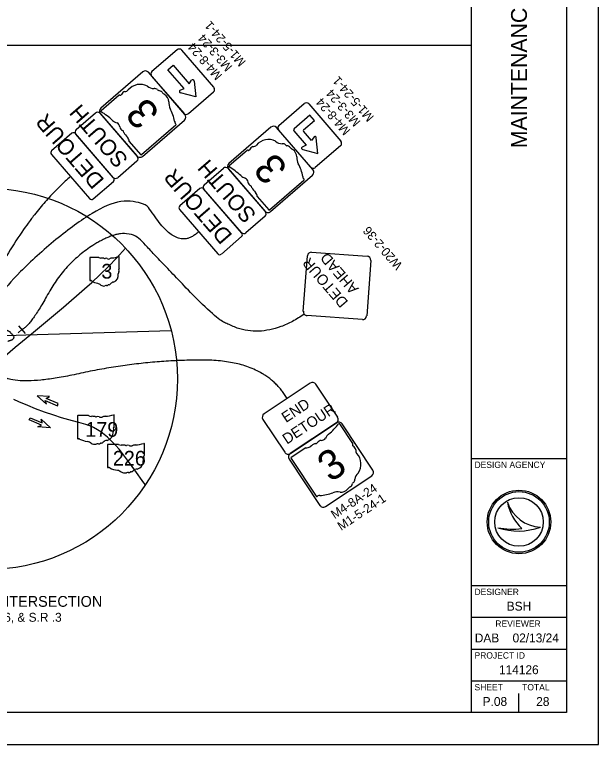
# Model space of a CAD drawing. Extents: x -15.3 to 34, y 0 to 22.
# Drawn here: x 24.81 to 34, y 0 to 11.48 of the extents above; entities that cross this region are included whole.
import ezdxf

# ---------------------------------------------------------------- set-up
doc = ezdxf.new("R2010")
doc.units = 0
for name, color, linetype in [('GM_X_State_Route', 7, 'Continuous'), ('GM_X_State_Shield', 7, 'Continuous'), ('GM_X_Township', 7, 'Continuous'), ('PM_P_Cells', 7, 'Continuous'), ('SC_Scratch1', 7, 'Continuous'), ('SH_Border', 7, 'Continuous'), ('SH_Cut_Line', 7, 'Continuous'), ('SH_Data', 7, 'Continuous'), ('SH_Text', 7, 'Continuous'), ('SN_P_Signs', 7, 'Continuous')]:
    doc.layers.add(name, color=color, linetype=linetype)

msp = doc.modelspace()

# ---------------------------------------------------------------- linework, layer by layer
at = {"layer": 'GM_X_State_Route'}
for points in [[(25.11, 6.489), (25.327, 6.672), (25.579, 6.881), (25.91, 7.167), (26.024, 7.269), (26.152, 7.389), (26.292, 7.526), (26.413, 7.653), (26.556, 7.81)], [(24.374, 5.874), (24.383, 5.882), (24.534, 6.008), (24.819, 6.248), (25.11, 6.489)], [(26.87, 4.084), (26.846, 4.118), (26.705, 4.313), (26.602, 4.454), (26.51, 4.577), (26.455, 4.645), (26.397, 4.71), (26.335, 4.773), (26.271, 4.833), (26.221, 4.876), (26.167, 4.916), (26.114, 4.952), (26.054, 4.984), (25.993, 5.01), (25.934, 5.031), (25.821, 5.064), (25.723, 5.091), (25.55, 5.141), (25.428, 5.178), (25.28, 5.23), (25.141, 5.282), (25.02, 5.331), (24.879, 5.392), (24.801, 5.429)]]:
    msp.add_lwpolyline(points, dxfattribs=at)
at = {"layer": 'GM_X_State_Shield'}
for p, q in [((25.995, 7.657), (25.995, 7.305)), ((26.136, 7.663), (26, 7.663)), ((26.459, 7.487), (26.459, 7.672)), ((26.459, 7.487), (26.459, 7.487)), ((25.976, 5.173), (25.806, 5.173)), ((26.38, 4.998), (26.38, 5.182)), ((25.8, 5.167), (25.8, 4.815)), ((26.38, 4.998), (26.38, 4.998)), ((26.273, 4.715), (26.273, 4.363)), ((26.448, 4.721), (26.279, 4.721)), ((26.853, 4.545), (26.853, 4.73)), ((26.853, 4.545), (26.853, 4.545))]:
    msp.add_line(p, q, dxfattribs=at)
for centre, radius, start, end in [((26, 7.658), 0.00538, 98.1301, 188.1301), ((26.168, 7.704), 0.0521, 231.6195, 271.1119), ((26.185, 7.465), 0.187, 80.4867, 94.9883), ((26.228, 7.659), 0.015, 219.7921, 297.1024), ((26.25, 7.619), 0.0313, 54.4667, 119.1411), ((26.29, 7.674), 0.0376, 233.8562, 294.8282), ((26.357, 7.555), 0.099, 97.3462, 120.7689), ((26.294, 8.143), 0.492, 275.8445, 288.9065), ((26.454, 7.672), 0.00517, 351.8621, 97.738), ((26.458, 7.474), 0.00799, 107.944, 210.337), ((26.407, 7.451), 0.048, 340.033, 23.6496), ((26.454, 7.487), 0.00553, 289.6038, 7.7341), ((26.321, 7.387), 0.123, 292.3089, 8.9858), ((26.478, 7.41), 0.0349, 136.8065, 186.9296), ((26, 7.304), 0.00542, 171.9584, 258.3066), ((26.001, 7.34), 0.0414, 267.339, 280.6039), ((26.01, 7.284), 0.0149, 29.7484, 93.2717), ((26.198, 7.601), 0.355, 240.4129, 257.1985), ((26.092, 7.146), 0.111, 47.1842, 75.836), ((26.288, 7.27), 0.0398, 282.8732, 323.2771), ((26.373, 7.206), 0.0674, 94.4031, 142.5768), ((26.212, 7.283), 0.0706, 230.7004, 286.2918), ((26.253, 7.161), 0.058, 85.6951, 111.2099), ((26.258, 7.256), 0.0376, 268.777, 315.5493), ((26.292, 7.222), 0.0106, 65.7517, 132.6484)]:
    msp.add_arc(centre, radius, start, end, dxfattribs=at)
for centre, major_axis, start_param, end_param in [((25.807, 5.168), (0.00672, 0), 1.712693, 3.28349), ((26.016, 5.214), (0.0652, 0), 4.042523, 4.731795), ((26.174, 5.653), (0.615, 0), 4.814394, 5.042369), ((26.374, 5.183), (0.00646, 0), 6.141152, 7.989035), ((26.038, 4.975), (0.234, 0), 1.404758, 1.657858), ((26.091, 5.17), (0.0188, 0), 3.836095, 5.185415), ((26.119, 5.129), (0.0391, 0), 0.950623, 2.079405), ((26.169, 5.185), (0.047, 0), 4.081561, 5.145723), ((26.252, 5.065), (0.124, 0), 1.699011, 2.107814), ((26.404, 4.92), (0.0436, 0), 2.387724, 3.262537), ((26.379, 4.984), (0.00999, 0), 1.883978, 3.671073), ((26.315, 4.961), (0.06, 0), 5.934695, 6.695948), ((26.374, 4.997), (0.00691, 0), 5.05454, 6.418171), ((26.208, 4.897), (0.154, 0), 5.101752, 6.440018), ((25.807, 4.814), (0.00678, 0), 3.00124, 4.508301), ((25.808, 4.85), (0.0517, 0), 4.665946, 4.897461), ((25.819, 4.794), (0.0187, 0), 0.519207, 1.627899), ((26.054, 5.111), (0.444, 0), 4.195997, 4.488961), ((25.922, 4.657), (0.139, 0), 0.823519, 1.323587), ((26.072, 4.793), (0.0882, 0), 4.026481, 4.996735), ((26.123, 4.671), (0.0725, 0), 1.495662, 1.94098), ((26.13, 4.766), (0.047, 0), 4.691044, 5.507374), ((26.172, 4.732), (0.0132, 0), 1.147584, 2.315152), ((26.166, 4.781), (0.0497, 0), 4.937069, 5.64225), ((26.273, 4.716), (0.0843, 0), 1.647645, 2.488434), ((26.28, 4.716), (0.00672, 0), 1.712693, 3.28349), ((26.489, 4.762), (0.0652, 0), 4.042523, 4.731795), ((26.511, 4.523), (0.234, 0), 1.404758, 1.657858), ((26.591, 4.677), (0.0391, 0), 0.950623, 2.079405), ((26.725, 4.613), (0.124, 0), 1.699011, 2.107814), ((26.646, 5.201), (0.615, 0), 4.814394, 5.042369), ((26.847, 4.73), (0.00646, 0), 6.141152, 7.989035), ((26.564, 4.717), (0.0188, 0), 3.836095, 5.185415), ((26.642, 4.733), (0.047, 0), 4.081561, 5.145723), ((26.876, 4.468), (0.0436, 0), 2.387724, 3.262537), ((26.851, 4.532), (0.00999, 0), 1.883978, 3.671073), ((26.788, 4.509), (0.06, 0), 5.934695, 6.695948), ((26.846, 4.545), (0.00691, 0), 5.05454, 6.418171), ((26.681, 4.445), (0.154, 0), 5.101752, 6.440018), ((26.28, 4.362), (0.00678, 0), 3.00124, 4.508301), ((26.281, 4.398), (0.0517, 0), 4.665946, 4.897461), ((26.291, 4.342), (0.0187, 0), 0.519207, 1.627899), ((26.527, 4.659), (0.444, 0), 4.195997, 4.488961), ((26.394, 4.204), (0.139, 0), 0.823519, 1.323587), ((26.545, 4.341), (0.0882, 0), 4.026481, 4.996735), ((26.596, 4.219), (0.0725, 0), 1.495662, 1.94098), ((26.602, 4.314), (0.047, 0), 4.691044, 5.507374), ((26.645, 4.28), (0.0132, 0), 1.147584, 2.315152), ((26.639, 4.328), (0.0497, 0), 4.937069, 5.64225), ((26.746, 4.264), (0.0843, 0), 1.647645, 2.488434)]:
    msp.add_ellipse(centre, major_axis=major_axis, ratio=0.8, start_param=start_param, end_param=end_param, dxfattribs=at)
at = {"layer": 'GM_X_Township'}
msp.add_lwpolyline([(21.433, 6.335), (21.992, 6.347), (24.231, 6.418), (24.989, 6.443), (27.276, 6.515)], dxfattribs=at)
at = {"layer": 'PM_P_Cells'}
for p, q in [((25.164, 5.487), (25.164, 5.487)), ((25.164, 5.487), (25.311, 5.353)), ((25.362, 5.473), (25.164, 5.487)), ((25.311, 5.353), (25.294, 5.41)), ((25.294, 5.41), (25.484, 5.329)), ((25.309, 5.445), (25.362, 5.473)), ((25.499, 5.364), (25.309, 5.445)), ((25.484, 5.329), (25.499, 5.364)), ((25.491, 5.346), (25.491, 5.346)), ((25.042, 5.106), (25.057, 5.14)), ((25.232, 5.025), (25.042, 5.106)), ((25.049, 5.123), (25.049, 5.123)), ((25.057, 5.14), (25.246, 5.059)), ((25.246, 5.059), (25.23, 5.116)), ((25.23, 5.116), (25.377, 4.983)), ((25.179, 4.997), (25.232, 5.025)), ((25.377, 4.983), (25.179, 4.997)), ((25.377, 4.983), (25.377, 4.983))]:
    msp.add_line(p, q, dxfattribs=at)
at = {"layer": 'SH_Border'}
for p, q in [((32, 0.5), (32, 21.5)), ((32, 4.5), (33.5, 4.5)), ((32, 2.5), (33.5, 2.5)), ((32, 2), (33.5, 2)), ((32, 1.5), (33.5, 1.5)), ((32, 1), (33.5, 1))]:
    msp.add_line(p, q, dxfattribs=at)
msp.add_lwpolyline([(1.5, 21.5), (33.5, 21.5), (33.5, 0.5), (1.5, 0.5)], close=True, dxfattribs=at)
at = {"layer": 'SH_Cut_Line'}
msp.add_lwpolyline([(0, 0), (34, 0), (34, 22), (0, 22)], close=True, dxfattribs=at)
at = {"layer": 'SH_Data'}
for p, q in [((32.567, 3.81), (32.567, 3.81)), ((32.75, 3.5), (32.75, 3.5)), ((32.417, 3.41), (32.417, 3.41)), ((33.087, 3.419), (33.087, 3.419)), ((32.75, 0.5), (32.75, 0.8)), ((32.375, 0.675), (32.375, 0.675))]:
    msp.add_line(p, q, dxfattribs=at)
for radius in [0.5, 0.477, 0.477, 0.382]:
    msp.add_circle((32.75, 3.5), radius, dxfattribs=at)
for centre, radius, start, end in [((33.116, 3.998), 0.58, 198.9257, 198.9319), ((33.347, 3.97), 0.796, 191.6379, 191.6421), ((33.116, 3.998), 0.58, 198.9319, 267.1657), ((33.347, 3.97), 0.796, 191.6421, 226.0947), ((32.739, 4.37), 1.013, 251.4576, 290.0832), ((32.648, 4.654), 1.266, 259.4964, 259.4995), ((32.739, 4.37), 1.013, 251.4527, 251.4576), ((32.648, 4.654), 1.266, 259.4995, 276.6672)]:
    msp.add_arc(centre, radius, start, end, dxfattribs=at)
at = {"layer": 'SH_Text'}
msp.add_line((1.5, 11), (32, 11), dxfattribs=at)
msp.add_circle((24.375, 5.75), 3, dxfattribs=at)
for points in [[(25.691, 8.936), (25.108, 8.44), (24.059, 6.582), (24.722, 6.238), (24.482, 6.158)], [(27.707, 8.067), (27.378, 7.746), (26.619, 8.935), (24.147, 6.818), (24.949, 6.395), (24.704, 6.342)], [(29.37, 6.769), (28.492, 6.169), (27.047, 7.664), (26.581, 8.173), (25.618, 7.599), (25.062, 6.587), (24.926, 6.527)], [(29.1, 5.444), (28.747, 6.047), (26.796, 6.047), (24.861, 5.622), (24.609, 5.799)]]:
    msp.add_open_spline(points, degree=2, dxfattribs=at)
at = {"layer": 'SN_P_Signs'}
for p, q in [((27.371, 10.93), (26.973, 10.587)), ((27.948, 10.339), (27.441, 10.925)), ((27.223, 10.616), (27.305, 10.688)), ((27.305, 10.688), (27.561, 10.392)), ((27.478, 10.321), (27.223, 10.616)), ((26.968, 10.516), (27.475, 9.93)), ((26.968, 10.516), (26.968, 10.516)), ((27.561, 10.392), (27.596, 10.449)), ((27.635, 10.437), (27.662, 10.191)), ((27.416, 10.294), (27.478, 10.321)), ((27.662, 10.191), (27.42, 10.254)), ((27.546, 9.925), (27.943, 10.268)), ((26.455, 10.215), (26.173, 9.971)), ((26.455, 10.215), (26.455, 10.215)), ((28.972, 9.739), (29.369, 10.082)), ((29.44, 10.077), (29.947, 9.491)), ((25.78, 9.674), (26.083, 9.935)), ((26.153, 9.93), (26.742, 9.249)), ((29.458, 9.901), (29.21, 9.686)), ((29.53, 9.818), (29.458, 9.901)), ((29.53, 9.818), (29.458, 9.901)), ((29.358, 9.67), (29.53, 9.818)), ((26.809, 9.282), (27.347, 9.747)), ((29.474, 9.082), (28.967, 9.668)), ((29.207, 9.653), (29.402, 9.428)), ((29.207, 9.653), (29.207, 9.653)), ((29.484, 9.5), (29.357, 9.648)), ((26.363, 8.922), (25.775, 9.603)), ((29.524, 9.562), (29.484, 9.5)), ((29.586, 9.299), (29.558, 9.544)), ((26.614, 9.488), (26.793, 9.281)), ((29.402, 9.428), (29.335, 9.398)), ((29.942, 9.42), (29.544, 9.077)), ((28.471, 9.346), (28.19, 9.103)), ((28.471, 9.346), (28.471, 9.346)), ((29.347, 9.362), (29.586, 9.299)), ((26.736, 9.179), (26.434, 8.917)), ((27.797, 8.805), (28.099, 9.067)), ((28.17, 9.062), (28.758, 8.381)), ((28.825, 8.413), (29.364, 8.878)), ((28.38, 8.054), (27.791, 8.735)), ((28.631, 8.62), (28.81, 8.412)), ((28.753, 8.31), (28.45, 8.049)), ((24.873, 6.587), (24.978, 6.466)), ((24.926, 6.527), (24.865, 6.474)), ((30.134, 4.732), (29.928, 5.042)), ((30.134, 4.732), (30.134, 4.732)), ((29.393, 4.666), (29.164, 4.515)), ((29.163, 4.499), (29.557, 3.906))]:
    msp.add_line(p, q, dxfattribs=at)
for points in [[(26.83, 10.581), (26.168, 10.009)], [(27.49, 9.913), (26.918, 10.575)], [(26.161, 9.921), (26.733, 9.259)], [(26.822, 9.252), (27.484, 9.824)], [(28.846, 9.713), (28.184, 9.14)], [(29.507, 9.044), (28.934, 9.706)], [(25.712, 9.615), (25.394, 9.34)], [(26.37, 8.915), (25.768, 9.611)], [(25.39, 9.284), (25.992, 8.588)], [(28.178, 9.052), (28.75, 8.39)], [(26.048, 8.584), (26.366, 8.858)], [(28.838, 8.384), (29.5, 8.956)], [(27.728, 8.746), (27.411, 8.472)], [(28.386, 8.046), (27.785, 8.742)], [(27.407, 8.415), (28.008, 7.719)], [(28.065, 7.715), (28.382, 7.99)], [(29.486, 7.745), (30.358, 7.681)], [(29.355, 6.814), (29.419, 7.687)], [(30.416, 7.614), (30.353, 6.742)], [(30.286, 6.684), (29.413, 6.748)], [(29.463, 5.684), (28.738, 5.203)], [(29.896, 5.149), (29.553, 5.666)], [(28.719, 5.113), (29.062, 4.597)], [(29.879, 5.061), (29.15, 4.577)], [(29.152, 4.578), (29.877, 5.059)], [(30.45, 4.314), (29.966, 5.043)], [(29.133, 4.49), (29.616, 3.761)], [(29.703, 3.744), (30.432, 4.227)]]:
    msp.add_lwpolyline(points, dxfattribs=at)
for centre, radius, start, end in [((27.403, 10.892), 0.05, 40.8371, 130.8371), ((26.87, 10.534), 0.0625, 40.8371, 130.8371), ((27.006, 10.549), 0.05, 130.8371, 220.8371), ((27.614, 10.438), 0.0209, 355.8276, 148.0417), ((26.79, 10.137), 0.249, 63.146, 139.823), ((26.999, 10.456), 0.136, 225.2403, 273.4139), ((27.91, 10.306), 0.05, 310.8371, 40.8371), ((26.477, 10.231), 0.0162, 238.7811, 341.1741), ((26.58, 10.184), 0.097, 110.8701, 154.4867), ((26.548, 10.345), 0.0705, 267.6436, 317.7667), ((27.012, 10.239), 0.0803, 53.7103, 94.1143), ((27.081, 10.31), 0.0214, 196.5889, 263.4856), ((27.073, 10.213), 0.0759, 39.6142, 86.3864), ((27.226, 10.331), 0.117, 216.5323, 242.0471), ((27.094, 10.108), 0.143, 1.5375, 57.129), ((27.425, 10.275), 0.0209, 113.6325, 255.4259), ((26.463, 10.207), 0.0112, 60.441, 138.5713), ((27.461, 10.104), 0.225, 178.0213, 206.6731), ((26.208, 9.962), 0.0625, 130.8371, 220.8371), ((26.626, 9.666), 0.718, 11.2501, 28.0356), ((29.402, 10.044), 0.05, 40.8371, 130.8371), ((26.115, 9.897), 0.05, 40.8371, 130.8371), ((26.179, 9.962), 0.0104, 122.6992, 228.5751), ((25.671, 9.096), 0.994, 46.6816, 59.7436), ((27.513, 9.963), 0.05, 220.8371, 310.8371), ((27.443, 9.872), 0.0625, 310.8371, 40.8371), ((26.486, 9.968), 0.2, 228.1833, 251.606), ((26.392, 9.709), 0.076, 4.6933, 65.6653), ((27.359, 9.796), 0.0302, 160.5855, 224.1089), ((27.285, 9.71), 0.0836, 38.1761, 51.441), ((27.341, 9.756), 0.011, 302.7955, 29.1438), ((25.813, 9.636), 0.05, 130.8371, 220.8371), ((26.531, 9.721), 0.0632, 185.3038, 249.9783), ((26.498, 9.634), 0.0304, 350.6292, 67.9395), ((28.887, 9.665), 0.0625, 40.8371, 130.8371), ((29.005, 9.701), 0.05, 130.8371, 220.8371), ((29.225, 9.668), 0.0234, 130.8371, 220.8371), ((29.369, 9.658), 0.0156, 130.8371, 220.8371), ((25.738, 9.585), 0.04, 40.8371, 130.8371), ((26.851, 9.825), 0.378, 211.3238, 225.8254), ((26.509, 9.484), 0.105, 2.4566, 41.949), ((29.538, 9.546), 0.0209, 355.8373, 130.8388), ((28.565, 9.476), 0.0705, 267.6436, 317.7667), ((28.807, 9.269), 0.249, 63.146, 139.823), ((29.015, 9.587), 0.136, 225.2403, 273.4139), ((29.029, 9.371), 0.0803, 53.7103, 94.1143), ((29.097, 9.442), 0.0214, 196.5889, 263.4856), ((29.09, 9.345), 0.0759, 39.6142, 86.3864), ((29.909, 9.458), 0.05, 310.8371, 40.8371), ((25.42, 9.31), 0.04, 130.8371, 220.8371), ((28.48, 9.339), 0.0112, 60.441, 138.5713), ((28.494, 9.362), 0.0162, 238.7811, 341.1741), ((28.596, 9.315), 0.097, 110.8701, 154.4867), ((29.243, 9.463), 0.117, 216.5323, 242.0471), ((29.11, 9.24), 0.143, 1.5375, 57.129), ((29.348, 9.382), 0.0209, 130.8388, 265.837), ((26.781, 9.3), 0.0625, 220.8371, 310.8371), ((26.704, 9.216), 0.05, 310.8371, 40.8371), ((26.801, 9.289), 0.0109, 228.9672, 318.9672), ((29.477, 9.236), 0.225, 178.0213, 206.6731), ((28.132, 9.029), 0.05, 40.8371, 130.8371), ((28.225, 9.093), 0.0625, 130.8371, 220.8371), ((28.195, 9.094), 0.0104, 122.6992, 228.5751), ((27.688, 8.227), 0.994, 46.6816, 59.7436), ((28.643, 8.798), 0.718, 11.2501, 28.0356), ((29.512, 9.115), 0.05, 220.8371, 310.8371), ((29.459, 9.003), 0.0625, 310.8371, 40.8371), ((26.401, 8.955), 0.05, 220.8371, 310.8371), ((26.34, 8.888), 0.04, 310.8371, 40.8371), ((28.503, 9.1), 0.2, 228.1833, 251.606), ((28.409, 8.841), 0.076, 4.6933, 65.6653), ((28.547, 8.853), 0.0632, 185.3038, 249.9783), ((29.375, 8.928), 0.0302, 160.5855, 224.1089), ((29.302, 8.841), 0.0836, 38.1761, 51.441), ((29.358, 8.888), 0.011, 302.7955, 29.1438), ((27.755, 8.716), 0.04, 40.8371, 130.8371), ((27.829, 8.767), 0.05, 130.8371, 220.8371), ((28.514, 8.765), 0.0304, 350.6292, 67.9395), ((28.867, 8.957), 0.378, 211.3238, 225.8254), ((28.525, 8.615), 0.105, 2.4566, 41.949), ((26.022, 8.614), 0.04, 220.8371, 310.8371), ((27.437, 8.442), 0.04, 130.8371, 220.8371), ((28.797, 8.431), 0.0625, 220.8371, 310.8371), ((28.817, 8.42), 0.0109, 228.9672, 318.9672), ((28.72, 8.348), 0.05, 310.8371, 40.8371), ((28.418, 8.087), 0.05, 220.8371, 310.8371), ((28.356, 8.02), 0.04, 310.8371, 40.8371), ((28.038, 7.745), 0.04, 220.8371, 310.8371), ((29.481, 7.683), 0.0625, 85.8371, 175.8371), ((30.354, 7.619), 0.0625, 355.8371, 85.8371), ((29.418, 6.81), 0.0625, 175.8371, 265.8371), ((30.29, 6.746), 0.0625, 265.8371, 355.8371), ((29.499, 5.63), 0.065, 33.5597, 123.5597), ((28.774, 5.149), 0.065, 123.5597, 213.5597), ((29.841, 5.113), 0.065, 303.5597, 33.5597), ((29.914, 5.009), 0.0625, 33.5597, 123.5597), ((29.123, 5.651), 0.994, 309.4042, 322.4662), ((29.919, 5.038), 0.0104, 25.4218, 131.2977), ((29.885, 4.732), 0.2, 130.9059, 154.3286), ((29.698, 4.389), 0.378, 114.0464, 128.548), ((29.552, 4.763), 0.0304, 253.3518, 330.6621), ((29.635, 4.719), 0.0632, 88.0264, 152.7008), ((29.64, 4.859), 0.076, 267.4159, 328.3879), ((30.147, 4.708), 0.0162, 141.5037, 243.8967), ((30.125, 4.725), 0.0112, 323.1635, 41.2938), ((29.116, 4.632), 0.065, 213.5597, 303.5597), ((29.402, 4.771), 0.105, 265.1792, 304.6716), ((30.087, 4.612), 0.097, 13.5927, 57.2093), ((30.251, 4.623), 0.0705, 170.3662, 220.4893), ((29.185, 4.525), 0.0625, 123.5597, 213.5597), ((29.172, 4.506), 0.0109, 131.6898, 221.6898), ((30.014, 4.409), 0.249, 325.8686, 42.5456), ((30.304, 4.162), 0.136, 127.9628, 176.1365), ((30.398, 4.279), 0.0625, 303.5597, 33.5597), ((30.088, 4.176), 0.0803, 316.4329, 356.8368), ((29.947, 4.112), 0.143, 264.2601, 319.8516), ((30.152, 3.952), 0.117, 119.2548, 144.7697), ((30.054, 4.119), 0.0759, 302.3367, 349.109), ((30.15, 4.099), 0.0214, 99.3114, 166.2081), ((29.567, 3.911), 0.011, 205.5181, 291.8663), ((29.528, 3.973), 0.0836, 300.8987, 314.1636), ((29.604, 3.888), 0.0302, 63.3081, 126.8315), ((29.568, 4.632), 0.718, 273.9726, 290.7582), ((29.897, 3.748), 0.225, 80.7439, 109.3957), ((29.668, 3.796), 0.0625, 213.5597, 303.5597)]:
    msp.add_arc(centre, radius, start, end, dxfattribs=at)

# ---------------------------------------------------------------- texts
at = {"layer": 'GM_X_State_Shield'}
for s, p in [('3', (26.177, 7.329)), ('179', (25.924, 4.84)), ('226', (26.358, 4.387))]:
    msp.add_text(s, height=0.232, dxfattribs=at).set_placement(p)
at = {"layer": 'SC_Scratch1'}
for s, rotation, p in [('M1-5-24-1', 130.8371, (28.459, 10.742)), ('M3-3-24', 130.8371, (28.247, 10.665)), ('M4-8-24', 130.8371, (28.088, 10.528)), ('M1-5-24-1', 130.8371, (30.475, 9.873)), ('M3-3-24', 130.8371, (30.264, 9.797)), ('M4-8-24', 130.8371, (30.105, 9.66)), ('W20-2-36', 130.8371, (30.925, 7.544)), ('M4-8A-24', 33.5597, (29.848, 3.543)), ('M1-5-24-1', 33.5597, (29.951, 3.359))]:
    msp.add_text(s, height=0.14, rotation=rotation, dxfattribs=at).set_placement(p)
at = {"layer": 'SH_Data'}
msp.add_text('MAINTENANCE OF TRAFFIC DETOUR PLAN', height=0.25, rotation=90, dxfattribs=at).set_placement((32.875, 9.381))
for s, height, p in [('DESIGN AGENCY', 0.1, (32.05, 4.35)), ('DESIGNER', 0.1, (32.05, 2.35)), ('BSH', 0.14, (32.557, 2.105)), ('REVIEWER', 0.1, (32.378, 1.85)), ('DAB', 0.14, (32.054, 1.605)), ('02/13/24', 0.14, (32.649, 1.605)), ('PROJECT ID', 0.1, (32.05, 1.35)), ('114126', 0.14, (32.435, 1.105)), ('SHEET', 0.1, (32.05, 0.85)), ('TOTAL', 0.1, (32.8, 0.85)), ('P.08', 0.14, (32.178, 0.605)), ('28', 0.14, (33.021, 0.605))]:
    msp.add_text(s, height=height, dxfattribs=at).set_placement(p)
at = {"layer": 'SH_Text'}
for s, height, p in [('DETAIL 4: DETOUR INTERSECTION', 0.17, (22.364, 2.165)), ('S.R. 179, S.R. 226, & S.R .3', 0.14, (23.19, 1.93))]:
    msp.add_text(s, height=height, dxfattribs=at).set_placement(p)
at = {"layer": 'SN_P_Signs'}
for s, height, rotation, p in [('3', 0.469, 130.8371, (27.112, 9.943)), ('SOUTH', 0.25, 130.8371, (26.611, 9.209)), ('DETOUR', 0.25, 130.8371, (26.235, 8.88)), ('SOUTH', 0.25, 130.8371, (28.628, 8.34)), ('3', 0.469, 130.8371, (29.128, 9.074)), ('DETOUR', 0.25, 130.8371, (28.252, 8.011)), ('AHEAD', 0.1667, 130.8371, (30.237, 7.174)), ('DETOUR', 0.1667, 130.8371, (30.07, 6.964)), ('END', 0.1667, 33.5597, (29.083, 5.056)), ('DETOUR', 0.1667, 33.5597, (29.097, 4.716)), ('3', 0.469, 33.5597, (29.781, 4.115))]:
    msp.add_text(s, height=height, rotation=rotation, dxfattribs=at).set_placement(p)

doc.saveas('drawing.dxf')
